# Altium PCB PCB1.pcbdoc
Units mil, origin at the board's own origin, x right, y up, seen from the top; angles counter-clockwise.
Board outline 2831.88 x 1405 mil, 2 copper layers (Top Layer, Bottom Layer); 11 components, 18 nets, 73 pads, 14 vias.
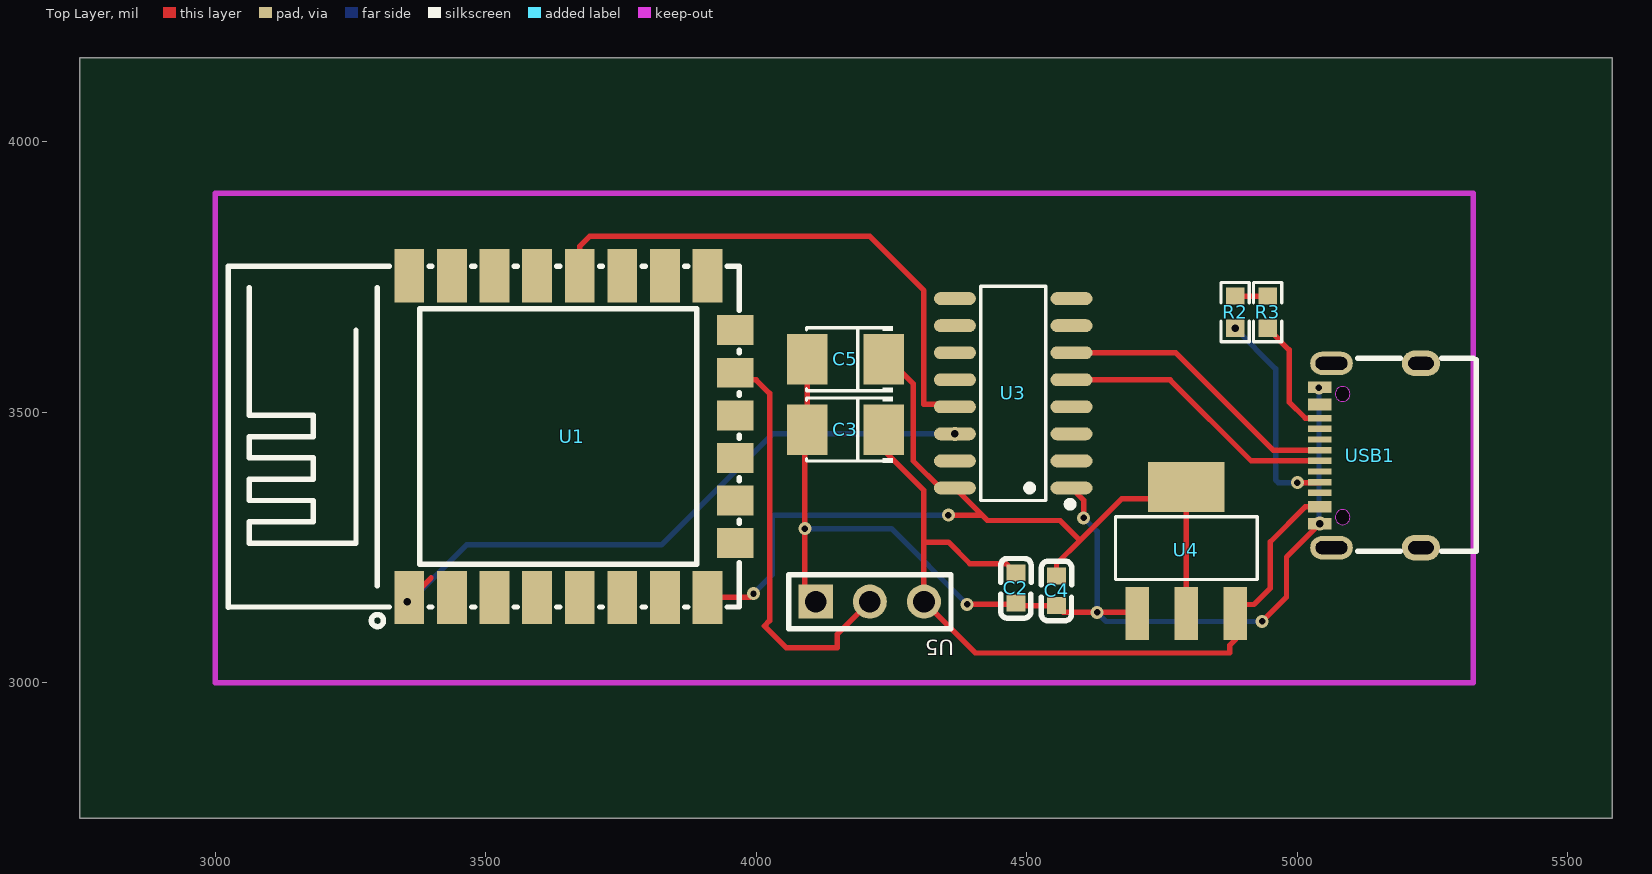
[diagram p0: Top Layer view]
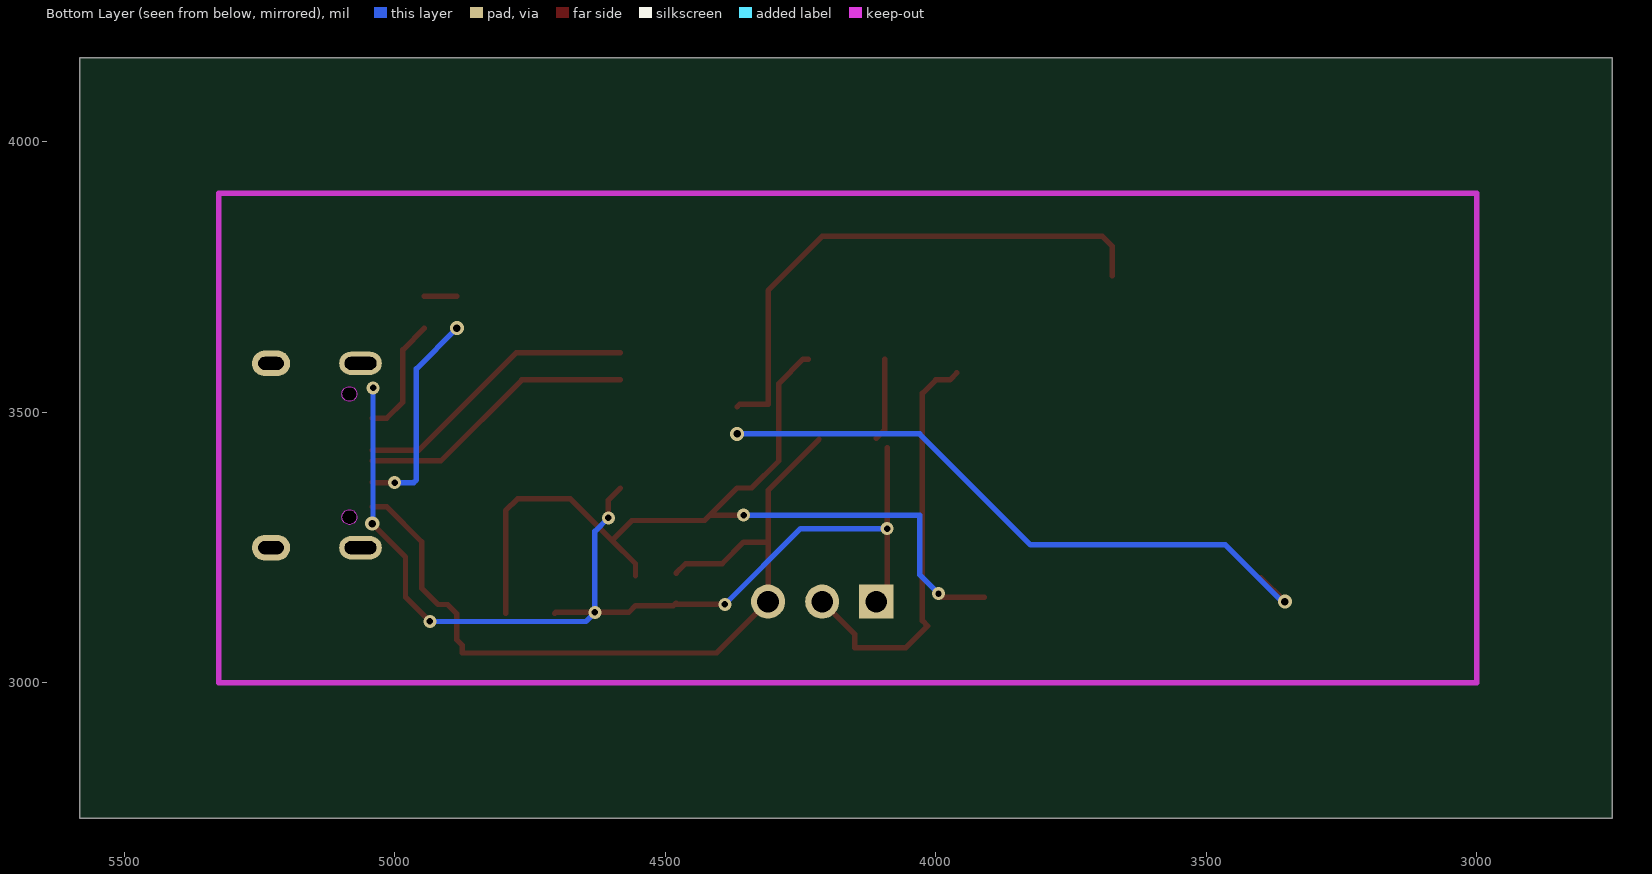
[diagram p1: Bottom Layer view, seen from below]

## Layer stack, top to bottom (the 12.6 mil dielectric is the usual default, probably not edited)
Top Layer: signal copper (thickness not stored)
Dielectric: dielectric 12.6, FR-4, Dk 4.8
Bottom Layer: signal copper (thickness not stored)

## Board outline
5581.88,2750 2750,2750 2750,4155 5581.88,4155

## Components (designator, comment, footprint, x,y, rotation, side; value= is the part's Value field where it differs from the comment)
C2 "100nF" C0603 4480,3175 r90 top
C3 "10uF" CAP-SMD_L3.5-W2.8-FD 4165,3467.97 r180 top
C4 "100nF" C0603 4555,3170 r90 top
C5 "10uF" CAP-SMD_L3.5-W2.8-FD 4165,3597.97 r180 top
R2 "5.1K" R0603 4885,3685 r270 top
R3 "5.1K" R0603 4945,3685 r270 top
U1 "ESP8266" WIFIM-SMD_ESP-12F-ESP8266MOD 3660,3455 r0 top
U3 "CH340G" SOIC-16_L9.9-W3.9-P1.27-LS6.0-BL 4475,3535 r90 top
U4 "AMS1117-3.3_C6186" SOT-223-3_L6.5-W3.4-P2.30-LS7.0-BR 4795,3245 r270 top
U5 "5-146480-3" HDR-TH_3P-P2.54-V-M-2 4210,3150 r180 top
USB1 "TYPE-C 16PIN 2MD(073)" USB-C-SMD_TYPE-C-6PIN-2MD-073 5135,3420 r90 top

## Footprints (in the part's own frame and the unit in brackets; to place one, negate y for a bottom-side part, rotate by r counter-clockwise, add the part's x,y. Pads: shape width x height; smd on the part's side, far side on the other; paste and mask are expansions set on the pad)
C0603 [mm]
  rect 0.8x0.9 smd: 1(-0.7,0) 2(0.7,0)
  silkscreen extent -1.41,-0.71 1.39,0.72
CAP-SMD_L3.5-W2.8-FD [mm]
  rect 1.9x2.376 smd: 1(-1.799,0) 2(1.799,0)
  silkscreen extent -2.21,-1.55 1.83,1.55
HDR-TH_3P-P2.54-V-M-2 [mm]
  rect 1.6x1.6 hole 1.02: 1(2.54,0)
  round 1.6 hole 1.02: 2(0,0) 3(-2.54,0)
  silkscreen extent -3.81,-1.27 3.81,1.27
R0603 [mil]
  rect 31.75x34.02 smd: 1(-29.66,0) 2(29.66,0)
  silkscreen extent -55,-26 55,26
SOIC-16_L9.9-W3.9-P1.27-LS6.0-BL [mil]
  oval 23.7x77.6 smd: 1(-175,-107.7) 2(-125,-107.7) 3(-75,-107.7) 4(-25,-107.7) 5(25,-107.7) 6(75,-107.7) 7(125,-107.7) 8(175,-107.7) 9(175,107.7) 10(125,107.7) 11(75,107.7) 12(25,107.7) 13(-25,107.7) 14(-75,107.7) 15(-125,107.7) 16(-175,107.7)
  silkscreen extent -211,-111 198,60
SOT-223-3_L6.5-W3.4-P2.30-LS7.0-BR [mm]
  rect 2.5x1.1 smd: 1(2.97,-2.3) 2(2.97,0) 3(2.97,2.3)
  rect 2.34x3.6 smd: 4(-2.97,0)
  silkscreen extent -1.57,-3.33 1.37,3.33
USB-C-SMD_TYPE-C-6PIN-2MD-073 [mm]
  rect 0.55x1.1 smd: 1(-3.2,2.375) 2(-2.4,2.375) 11(2.4,2.375) 12(3.2,2.375)
  rect 0.3x1.1 smd: 3(-1.75,2.375) 4(-1.25,2.375) 5(-0.75,2.375) 6(-0.25,2.375) 7(0.25,2.375) 8(0.75,2.375) 9(1.25,2.375) 10(1.75,2.375)
  oval 1.2x1.8 hole 0.6 slot 1.2 at 90 deg: 13(-4.325,-2.375) 14(4.325,-2.375)
  oval 1.1x2 hole 0.6 slot 1.5 at 90 deg: 13(-4.325,1.825) 14(4.325,1.825)
  Multi-Layer board cut-out: -2.89,0.955 -2.738,0.99 -2.616,1.087 -2.549,1.227 -2.549,1.383 -2.616,1.523 -2.738,1.62 -2.89,1.655 -2.89,1.655 -3.042,1.62 -3.163,1.523 -3.231,1.383 -3.231,1.227 -3.164,1.087 -3.042,0.99 -2.89,0.955
  Multi-Layer board cut-out: 2.89,0.955 3.042,0.99 3.164,1.087 3.231,1.227 3.232,1.383 3.164,1.523 3.042,1.62 2.89,1.655 2.89,1.655 2.738,1.62 2.617,1.523 2.549,1.383 2.549,1.227 2.616,1.087 2.738,0.99 2.89,0.955
  Multi-Layer keep-out region: -2.89,0.955 -2.738,0.99 -2.616,1.087 -2.549,1.227 -2.549,1.383 -2.616,1.523 -2.738,1.62 -2.89,1.655 -2.89,1.655 -3.042,1.62 -3.163,1.523 -3.231,1.383 -3.231,1.227 -3.164,1.087 -3.042,0.99 -2.89,0.955
  Multi-Layer keep-out region: 2.89,0.955 3.042,0.99 3.164,1.087 3.231,1.227 3.232,1.383 3.164,1.523 3.042,1.62 2.89,1.655 2.89,1.655 2.738,1.62 2.617,1.523 2.549,1.383 2.549,1.227 2.616,1.087 2.738,0.99 2.89,0.955
  silkscreen extent -4.5,-4.97 4.57,0.6
WIFIM-SMD_ESP-12F-ESP8266MOD [mm]
  rect 1.4x2.5 smd: 1(-7.651,-7.551) 2(-5.651,-7.551) 3(-3.651,-7.551) 4(-1.651,-7.551) 5(0.349,-7.551) 6(2.349,-7.551) 7(4.349,-7.551) 8(6.349,-7.551) 9(6.349,7.549) 10(4.349,7.55) 11(2.349,7.551) 12(0.349,7.551) 13(-1.651,7.55) 14(-3.651,7.551) 15(-5.651,7.55) 16(-7.651,7.551)
  rect 1.7x1.4 smd: 17(7.651,-5) 18(7.649,-3.002) 19(7.65,-1.003) 20(7.65,0.997) 21(7.65,2.997) 22(7.65,4.997)
  silkscreen extent -16.15,-8.92 7.85,8

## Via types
v1: diameter 24, hole 12, Top Layer to Bottom Layer, 10 vias
v2: diameter 26, hole 14, Top Layer to Bottom Layer, 4 vias

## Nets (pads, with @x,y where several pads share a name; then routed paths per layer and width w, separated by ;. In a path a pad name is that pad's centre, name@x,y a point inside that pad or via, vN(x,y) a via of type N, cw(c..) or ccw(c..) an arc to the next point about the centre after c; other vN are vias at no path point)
$1N627: U1.9
$1N668: U3.3
$1N671: U3.2
$1N1117: USB1.3
$1N1344: R3.2 USB1.10 | length 222
  Top Layer w10: R3.2 4985,3615.34 4985,3518.75 5014.84,3488.91 USB1.10
$1N1352: R2.2 USB1.4 | length 395.3
  Top Layer w10: v1(5000,3370) 5040.7,3370 USB1.4
  Bottom Layer w10: v2(4885,3655.34) 4960,3580.34 4960,3375 4965,3370 v1(5000,3370)
$1N1393: R2.1 R3.1 | length 60
  Top Layer w10: R2.1 R3.1
BT0: U1.12 U3.13 | length 1008.9
  Top Layer w10: U1.12 3673.76,3806.48 3692.27,3825 4210,3825 4310,3725 4310,3515 4362.3,3515 U3.13
DO: U1.21 U5.2 | length 775.1
  Top Layer w10: U1.21 3974.14,3560 4000,3560 4025,3535 4025,3115 4015,3105 4055,3065 4150,3065 4150,3090 U5.2
GND: C2.1 C3.2 C4.1 C5.2 U3.1 U4.1 U5.1 USB1.1 USB1.12 | length 2166.1
  Top Layer w10: C3.2@4090,3434.19 v1(4090,3285) 4090,3170 U5.1 ; C5.2 C3.2 C3.2@4110,3452.16 ; v1(4390,3145) 4477.56,3145 C2.1 4485,3142.44 C4.1 4567.44,3130 v1(4630,3130) 4702.52,3130 U4.1 ; U3.1 4605,3337.7 v1(4605,3305) ; v1(4935,3113.35) 4980,3158.35 4980,3232.52 v1(5041.49,3294.01) ; v1(5040,3545) 5040.51,3545 USB1.12
  Bottom Layer w10: v1(4090,3285) 4250,3285 v1(4390,3145) ; v1(4605,3305) 4630,3280 v1(4630,3130) 4646.65,3113.35 v1(4935,3113.35) ; v1(5040,3545) 5040,3295.51 v1(5041.49,3294.01)
  other v2: 5041.49,3294.01
RST: U1.1 U3.14 | length 1210
  Top Layer w10: v2(3355,3150) 3398.99,3193.99
  Bottom Layer w10: v2(3355,3150) 3355,3145 3465,3255 3825,3255 4030,3460 v2(4367.3,3460)
RX: U1.15
TX: U1.16
UD+: U3.5 USB1.6 | length 520.9
  Top Layer w10: U3.5 4765,3560 4914.85,3410.16 USB1.6
UD-: U3.6 USB1.7 | length 533.4
  Top Layer w10: U3.6 4775,3610 4955.15,3429.84 USB1.7
VCC: C2.2 C3.1 U4.3 U5.3 USB1.2 | length 1502.5
  Top Layer w10: C3.1@4215.81,3450 4310,3355.81 4310,3260 ; C2.2 4462.56,3220 4395,3220 4355,3260 4310,3260 ; USB1.2 5014.84,3325.51 4950,3260.67 4950,3175 4919.68,3144.68 4902.15,3144.68 U4.3 4885.55,3079.69 4875,3069.14 4875,3055 4405,3055 U5.3 4310,3260
VOUT: C4.2 C5.1 U1.8 U3.16 U4.2 U4.4 | length 1730.7
  Top Layer w10: U1.8 3987.73,3157.73 v1(3995,3165) ; C5.1 4245,3597.97 4290,3552.97 4290,3410.35 4340.35,3360 U3.16 4417.3,3310 ; v1(4355,3310) 4417.3,3310 ; C4.2 4555,3220 4598.33,3263.33 ; U4.2 4795,3318.07 4773.07,3340 4675,3340 4598.33,3263.33 ; 4417.3,3310 4427.3,3300 4561.65,3300 4598.33,3263.33
  Bottom Layer w10: v1(3995,3165) 4030,3200 4030,3310 v1(4355,3310)
"": U1.2 U1.3 U1.4 U1.5 U1.6 U1.7 U1.10 U1.11 U1.13 U1.14 U1.17 U1.18 U1.19 U1.20 U1.22 U3.4 U3.7 U3.8 U3.9 U3.10 U3.11 U3.12 U3.15 USB1.5 USB1.8 USB1.9 USB1.11 USB1.13 USB1.14

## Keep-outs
Board Outline Layer:
  lines w10 net "": 3000,3000 5325,3000 5325,3905 3000,3905 3000,3000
